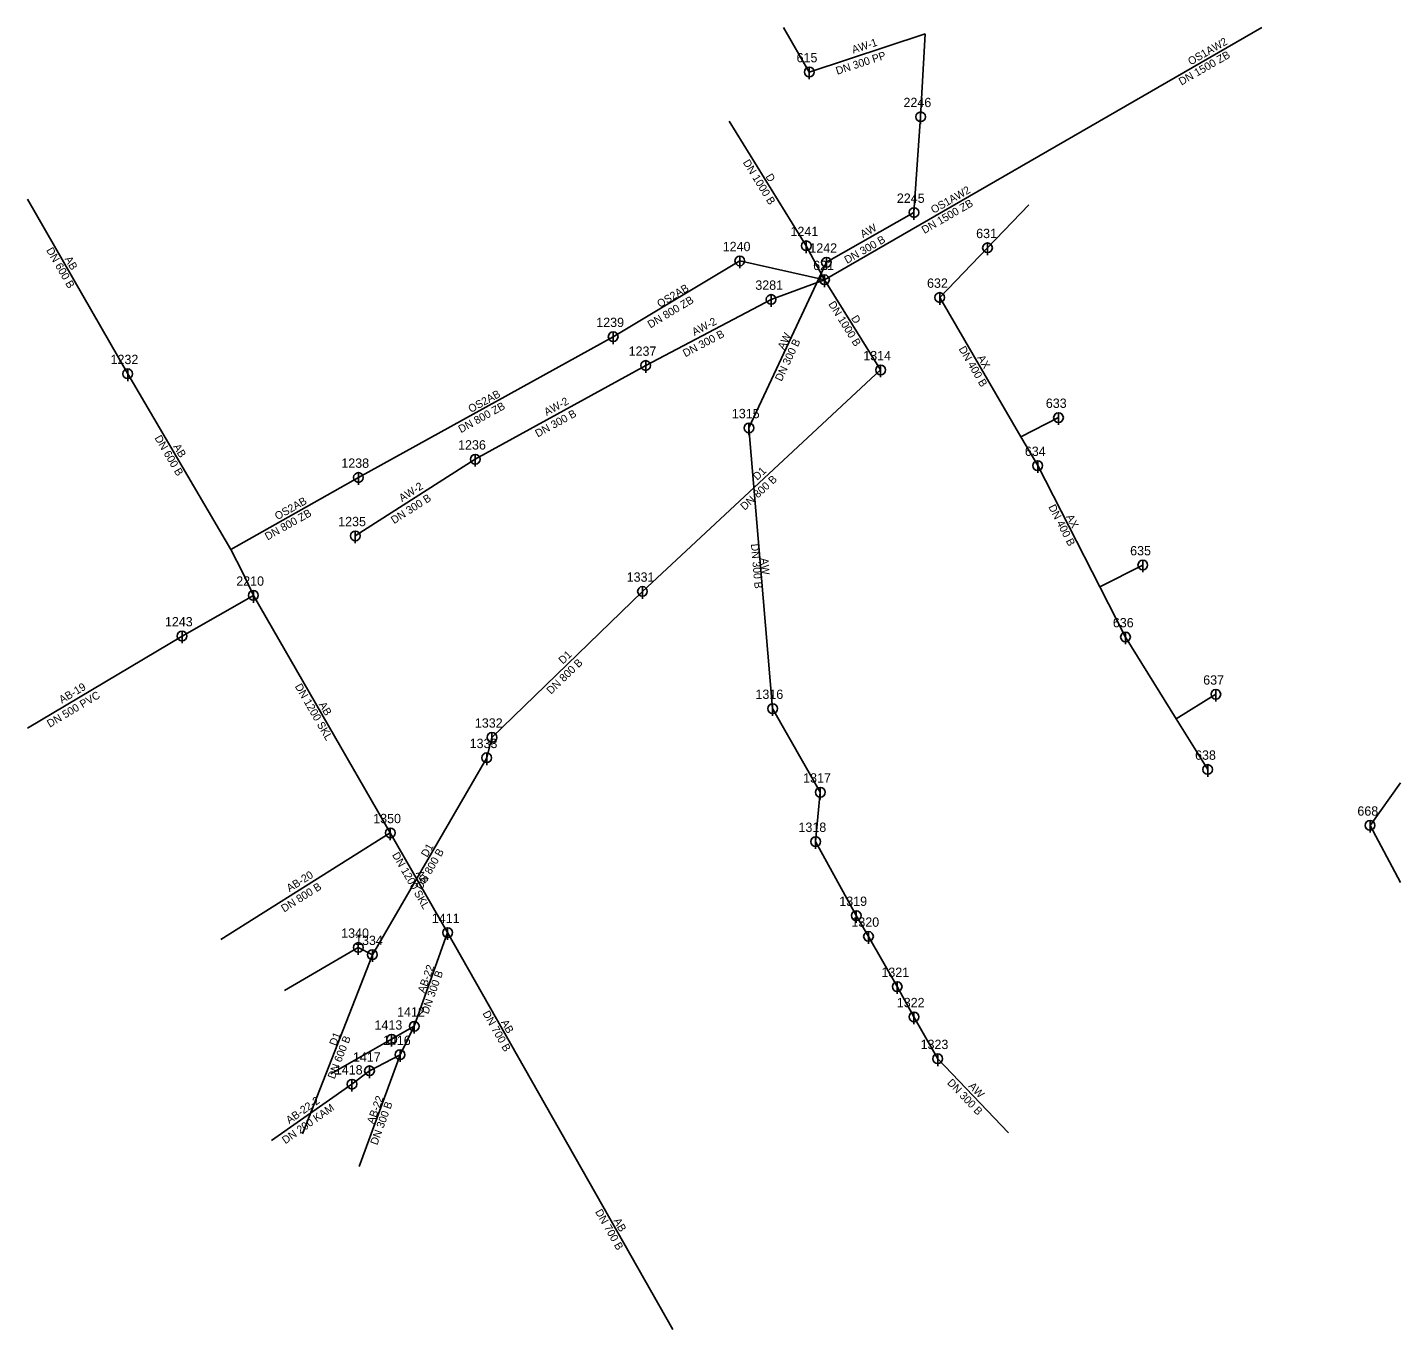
# Model space of a CAD drawing. Extents: x -443910 to -443627, y -1122538 to -1122269.
import ezdxf

# ---------------------------------------------------------------- set-up
doc = ezdxf.new("R2010")
doc.units = 0
for name, color, linetype in [('_odlehcovaci_stoka_smvak_z_dokumentace_', 7, 'Continuous'), ('_stoka_destova_smvak_prevzato_z_dokumentace_', 7, 'Continuous'), ('_stoka_jednotna_smvak_prevzato_z_dokumentace_', 7, 'Continuous'), ('Default', 7, 'Continuous'), ('MoLevel 117', 7, 'Continuous'), ('MoLevel 118', 7, 'Continuous'), ('MoLevel 119', 7, 'Continuous'), ('MoLevel 120', 7, 'Continuous'), ('MoLevel 68', 7, 'Continuous'), ('MoLevel 69', 7, 'Continuous'), ('MoLevel 74', 7, 'Continuous'), ('MoLevel 75', 7, 'Continuous')]:
    doc.layers.add(name, color=color, linetype=linetype)

# ---------------------------------------------------------------- blocks, each defined once
blk = doc.blocks.new('_sachta_kanal_prevzato_z_dokumentace_')
at = {"layer": 'Default'}
blk.add_line((0, 0.00005), (0, -0.000075), dxfattribs=at)
blk.add_circle((0, 0), 0.00005, dxfattribs=at)

msp = doc.modelspace()

# ---------------------------------------------------------------- linework, layer by layer
at = {"layer": '_odlehcovaci_stoka_smvak_z_dokumentace_'}
for p, q in [((-443745.69, -1122321.46), (-443655.46, -1122269.37)), ((-443789.31, -1122333.22), (-443763.17, -1122317.56)), ((-443763.17, -1122317.56), (-443745.69, -1122321.46)), ((-443756.71, -1122325.53), (-443745.69, -1122321.46)), ((-443841.88, -1122362.28), (-443789.31, -1122333.22)), ((-443868.19, -1122377.11), (-443841.88, -1122362.28))]:
    msp.add_line(p, q, dxfattribs=at)
at = {"layer": '_stoka_destova_smvak_prevzato_z_dokumentace_'}
for p, q in [((-443765.35, -1122288.72), (-443749.45, -1122314.45)), ((-443749.45, -1122314.45), (-443745.69, -1122321.46)), ((-443734.12, -1122340.08), (-443745.69, -1122321.46)), ((-443782.59, -1122339.16), (-443756.71, -1122325.53)), ((-443817.78, -1122358.51), (-443782.59, -1122339.16)), ((-443783.26, -1122385.8), (-443734.12, -1122340.08)), ((-443842.53, -1122374.33), (-443817.78, -1122358.51)), ((-443814.32, -1122415.92), (-443783.26, -1122385.8)), ((-443815.4, -1122420.14), (-443814.32, -1122415.92)), ((-443839, -1122460.79), (-443815.4, -1122420.14)), ((-443857.15, -1122468.18), (-443841.91, -1122459.3)), ((-443853.43, -1122497.8), (-443839, -1122460.79)), ((-443841.91, -1122459.3), (-443839, -1122460.79))]:
    msp.add_line(p, q, dxfattribs=at)
at = {"layer": '_stoka_jednotna_smvak_prevzato_z_dokumentace_'}
for p, q in [((-443754.15, -1122269.37), (-443748.84, -1122278.57)), ((-443748.84, -1122278.57), (-443724.93, -1122270.71)), ((-443725.86, -1122287.82), (-443724.93, -1122270.71)), ((-443727.23, -1122307.58), (-443725.86, -1122287.82)), ((-443889.51, -1122340.87), (-443910.19, -1122304.82)), ((-443745.29, -1122317.86), (-443727.23, -1122307.58)), ((-443712.05, -1122314.86), (-443703.54, -1122305.96)), ((-443721.92, -1122325.12), (-443712.05, -1122314.86)), ((-443761.28, -1122352.04), (-443745.29, -1122317.86)), ((-443705.14, -1122353.89), (-443721.92, -1122325.12)), ((-443868.19, -1122377.11), (-443889.51, -1122340.87)), ((-443697.4, -1122349.91), (-443705.14, -1122353.89)), ((-443756.41, -1122409.99), (-443761.28, -1122352.04)), ((-443701.68, -1122359.83), (-443705.14, -1122353.89)), ((-443688.86, -1122384.88), (-443701.68, -1122359.83)), ((-443865.77, -1122381.98), (-443868.19, -1122377.11)), ((-443863.57, -1122386.62), (-443865.77, -1122381.98)), ((-443680, -1122380.35), (-443688.86, -1122384.88)), ((-443683.57, -1122395.21), (-443688.86, -1122384.88)), ((-443878.29, -1122395.01), (-443863.57, -1122386.62)), ((-443835.3, -1122435.64), (-443863.57, -1122386.62)), ((-443910.19, -1122414.02), (-443878.29, -1122395.01)), ((-443673.08, -1122412.11), (-443683.57, -1122395.21)), ((-443664.92, -1122407.04), (-443673.08, -1122412.11)), ((-443746.57, -1122427.26), (-443756.41, -1122409.99)), ((-443666.6, -1122422.55), (-443673.08, -1122412.11)), ((-443747.53, -1122437.44), (-443746.57, -1122427.26)), ((-443633.1, -1122434.09), (-443626.81, -1122425.34)), ((-443870.29, -1122457.62), (-443835.3, -1122435.64)), ((-443823.47, -1122456.23), (-443835.3, -1122435.64)), ((-443626.81, -1122445.89), (-443633.1, -1122434.09)), ((-443739.15, -1122452.72), (-443747.53, -1122437.44)), ((-443736.61, -1122457.02), (-443739.15, -1122452.72)), ((-443830.37, -1122475.56), (-443823.47, -1122456.23)), ((-443777.01, -1122538.17), (-443823.47, -1122456.23)), ((-443730.69, -1122467.38), (-443736.61, -1122457.02)), ((-443727.24, -1122473.63), (-443730.69, -1122467.38)), ((-443835.03, -1122478.26), (-443830.37, -1122475.56)), ((-443833.29, -1122481.43), (-443830.37, -1122475.56)), ((-443722.33, -1122482.27), (-443727.24, -1122473.63)), ((-443847.56, -1122485.36), (-443835.03, -1122478.26)), ((-443841.72, -1122504.52), (-443833.29, -1122481.43)), ((-443839.6, -1122484.76), (-443833.29, -1122481.43)), ((-443707.74, -1122497.59), (-443722.33, -1122482.27)), ((-443843.22, -1122487.52), (-443839.6, -1122484.76)), ((-443859.8, -1122499.17), (-443843.22, -1122487.52))]:
    msp.add_line(p, q, dxfattribs=at)

# ---------------------------------------------------------------- block references
at = {"layer": 'MoLevel 119', "xscale": 20000, "yscale": 20000}
for p in [(-443748.84, -1122278.57), (-443725.86, -1122287.82), (-443727.23, -1122307.58), (-443749.45, -1122314.45), (-443712.05, -1122314.86), (-443763.17, -1122317.56), (-443745.29, -1122317.86), (-443745.69, -1122321.46), (-443756.71, -1122325.53), (-443721.92, -1122325.12), (-443789.31, -1122333.22), (-443889.51, -1122340.87), (-443782.59, -1122339.16), (-443734.12, -1122340.08), (-443761.28, -1122352.04), (-443697.4, -1122349.91), (-443817.78, -1122358.51), (-443701.68, -1122359.83), (-443841.88, -1122362.28), (-443842.53, -1122374.33), (-443680, -1122380.35), (-443783.26, -1122385.8), (-443863.57, -1122386.62), (-443878.29, -1122395.01), (-443683.57, -1122395.21), (-443664.92, -1122407.04), (-443756.41, -1122409.99), (-443814.32, -1122415.92), (-443815.4, -1122420.14), (-443666.6, -1122422.55), (-443746.57, -1122427.26), (-443633.1, -1122434.09), (-443835.3, -1122435.64), (-443747.53, -1122437.44), (-443739.15, -1122452.72), (-443823.47, -1122456.23), (-443736.61, -1122457.02), (-443841.91, -1122459.3), (-443839, -1122460.79), (-443730.69, -1122467.38), (-443727.24, -1122473.63), (-443830.37, -1122475.56), (-443835.03, -1122478.26), (-443833.29, -1122481.43), (-443722.33, -1122482.27), (-443839.6, -1122484.76), (-443843.22, -1122487.52)]:
    msp.add_blockref('_sachta_kanal_prevzato_z_dokumentace_', p, dxfattribs=at)

# ---------------------------------------------------------------- texts
at = {"layer": 'MoLevel 117'}
for s, rotation, p in [('DN 1500 ZB', 29.9949, (-443672.02, -1122281.39)), ('DN 1500 ZB', 29.9949, (-443725.08, -1122312.02)), ('DN 800 ZB', 30.9251, (-443781.62, -1122331.53)), ('DN 800 ZB', 28.9329, (-443820.73, -1122353.14)), ('DN 800 ZB', 29.4113, (-443860.64, -1122375.3))]:
    msp.add_text(s, height=1.605, rotation=rotation, dxfattribs=at).set_placement(p)
at = {"layer": 'MoLevel 118'}
for s, rotation, p in [('OS1AW2', 29.9949, (-443670.11, -1122277.23)), ('OS1AW2', 29.9949, (-443723.17, -1122307.86)), ('OS2AB', 30.9251, (-443779.66, -1122327.29)), ('OS2AB', 28.9329, (-443818.67, -1122348.97)), ('OS2AB', 29.4113, (-443858.6, -1122371.11))]:
    msp.add_text(s, height=1.605, rotation=rotation, dxfattribs=at).set_placement(p)
at = {"layer": 'MoLevel 120'}
for s, p in [('615', (-443751.45, -1122276.57)), ('2246', (-443729.39, -1122285.82)), ('2245', (-443730.76, -1122305.58)), ('1241', (-443752.71, -1122312.45)), ('631', (-443714.39, -1122312.86)), ('1240', (-443766.7, -1122315.56)), ('1242', (-443748.82, -1122315.86)), ('621', (-443748.03, -1122319.46)), ('3281', (-443759.97, -1122323.53)), ('632', (-443724.53, -1122323.12)), ('1239', (-443792.8, -1122331.22)), ('1232', (-443893.04, -1122338.87)), ('1237', (-443786.12, -1122337.16)), ('1314', (-443737.69, -1122338.08)), ('1315', (-443764.81, -1122350.04)), ('633', (-443700.01, -1122347.91)), ('1236', (-443821.31, -1122356.51)), ('634', (-443704.34, -1122357.83)), ('1238', (-443845.41, -1122360.28)), ('1235', (-443846.06, -1122372.33)), ('635', (-443682.61, -1122378.35)), ('1331', (-443786.52, -1122383.8)), ('2210', (-443867.1, -1122384.62)), ('1243', (-443881.82, -1122393.01)), ('636', (-443686.18, -1122393.21)), ('637', (-443667.53, -1122405.04)), ('1316', (-443759.94, -1122407.99)), ('1332', (-443817.85, -1122413.92)), ('1333', (-443818.93, -1122418.14)), ('638', (-443669.21, -1122420.55)), ('1317', (-443750.1, -1122425.26)), ('668', (-443635.71, -1122432.09)), ('1350', (-443838.83, -1122433.64)), ('1318', (-443751.06, -1122435.44)), ('1319', (-443742.64, -1122450.72)), ('1411', (-443826.73, -1122454.23)), ('1320', (-443740.14, -1122455.02)), ('1340', (-443845.44, -1122457.3)), ('1334', (-443842.58, -1122458.79)), ('1321', (-443733.95, -1122465.38)), ('1322', (-443730.77, -1122471.63)), ('1412', (-443833.9, -1122473.56)), ('1413', (-443838.56, -1122476.26)), ('1416', (-443836.82, -1122479.43)), ('1323', (-443725.86, -1122480.27)), ('1417', (-443843.02, -1122482.88)), ('1418', (-443846.75, -1122485.52))]:
    msp.add_text(s, height=1.926, dxfattribs=at).set_placement(p)
at = {"layer": 'MoLevel 68'}
for s, height, rotation, p in [('DN 300 PP', 1.605, 18.1974, (-443743.06, -1122279.16)), ('DN 300 B', 1.605, 29.6479, (-443741.04, -1122318.21)), ('DN 600 B', 1.605, 299.8449, (-443906.38, -1122315.34)), ('DN 300 B', 1.605, 64.9261, (-443754.55, -1122342.56)), ('DN 400 B', 1.605, 300.2468, (-443718.06, -1122335.73)), ('DN 600 B', 1.605, 300.4599, (-443884.02, -1122354.12)), ('DN 400 B', 1.605, 297.1068, (-443699.53, -1122368.34)), ('DN 300 B', 1.605, 274.805, (-443760.88, -1122376.01)), ('DN 1200 SKL', 1.6049, 299.9722, (-443855.06, -1122405.38)), ('DN 500 PVC', 1.605, 30.7948, (-443905.58, -1122413.95)), ('DN 1200 SKL', 1.6049, 299.8808, (-443835, -1122440.18)), ('DN 800 B', 1.605, 32.1362, (-443857.22, -1122452.1)), ('DN 300 B', 1.605, 70.3548, (-443827.49, -1122473.17)), ('DN 700 B', 1.605, 299.553, (-443816.32, -1122472.89)), ('DN 300 B', 1.605, 313.6019, (-443720.49, -1122487.33)), ('DN 200 KAM', 1.605, 35.0956, (-443856.96, -1122499.94)), ('DN 300 B', 1.605, 69.9446, (-443838, -1122500.21)), ('DN 700 B', 1.605, 299.553, (-443793.09, -1122513.86))]:
    msp.add_text(s, height=height, rotation=rotation, dxfattribs=at).set_placement(p)
at = {"layer": 'MoLevel 69'}
for s, rotation, p in [('AW-1', 18.1974, (-443739.75, -1122274.78)), ('AW', 29.6479, (-443737.75, -1122312.89)), ('AB', 299.8449, (-443902.57, -1122317.15)), ('AW', 64.9261, (-443754.01, -1122336.02)), ('AX', 300.2468, (-443714.21, -1122337.55)), ('AB', 300.4599, (-443880.17, -1122355.89)), ('AX', 297.1068, (-443695.88, -1122370.37)), ('AW', 274.805, (-443758.89, -1122378.96)), ('AB-19', 30.7948, (-443903.09, -1122408.99)), ('AB', 299.9722, (-443850.12, -1122409.14)), ('AB-20', 32.1362, (-443856.1, -1122447.9)), ('AB', 299.8808, (-443830.07, -1122443.94)), ('AB-22', 70.3548, (-443828.22, -1122468.83)), ('AB', 299.553, (-443812.53, -1122474.72)), ('AB-22', 69.9446, (-443838.71, -1122495.87)), ('AW', 313.6019, (-443716.09, -1122488.02)), ('AB-22-2', 35.0956, (-443856.14, -1122495.8)), ('AB', 299.553, (-443789.3, -1122515.69))]:
    msp.add_text(s, height=1.605, rotation=rotation, dxfattribs=at).set_placement(p)
at = {"layer": 'MoLevel 74'}
for s, rotation, p in [('DN 1000 B', 301.7158, (-443762.6, -1122297.23)), ('DN 1000 B', 301.8619, (-443744.96, -1122326.48)), ('DN 300 B', 27.782, (-443774.42, -1122337.47)), ('DN 300 B', 28.8068, (-443804.87, -1122354.04)), ('DN 800 B', 42.9316, (-443762.16, -1122369.16)), ('DN 300 B', 32.5883, (-443834.54, -1122371.93)), ('DN 800 B', 44.1197, (-443802.14, -1122407.15)), ('DN 800 B', 59.862, (-443828.83, -1122447.53)), ('DN 600 B', 68.6995, (-443846.81, -1122486.58))]:
    msp.add_text(s, height=1.605, rotation=rotation, dxfattribs=at).set_placement(p)
at = {"layer": 'MoLevel 75'}
for s, height, rotation, p in [('D', 1.6, 301.7158, (-443757.92, -1122300.15)), ('AW-2', 1.605, 27.782, (-443772.53, -1122333.06)), ('D', 1.6, 301.8619, (-443740.27, -1122329.39)), ('AW-2', 1.605, 28.8068, (-443803.03, -1122349.6)), ('D1', 1.605, 42.9316, (-443759.58, -1122362.97)), ('AW-2', 1.605, 32.5883, (-443832.89, -1122367.37)), ('D1', 1.605, 44.1197, (-443799.67, -1122400.91)), ('D1', 1.605, 59.862, (-443827.7, -1122440.8)), ('D1', 1.605, 68.6995, (-443846.48, -1122479.73))]:
    msp.add_text(s, height=height, rotation=rotation, dxfattribs=at).set_placement(p)

doc.saveas('drawing.dxf')
